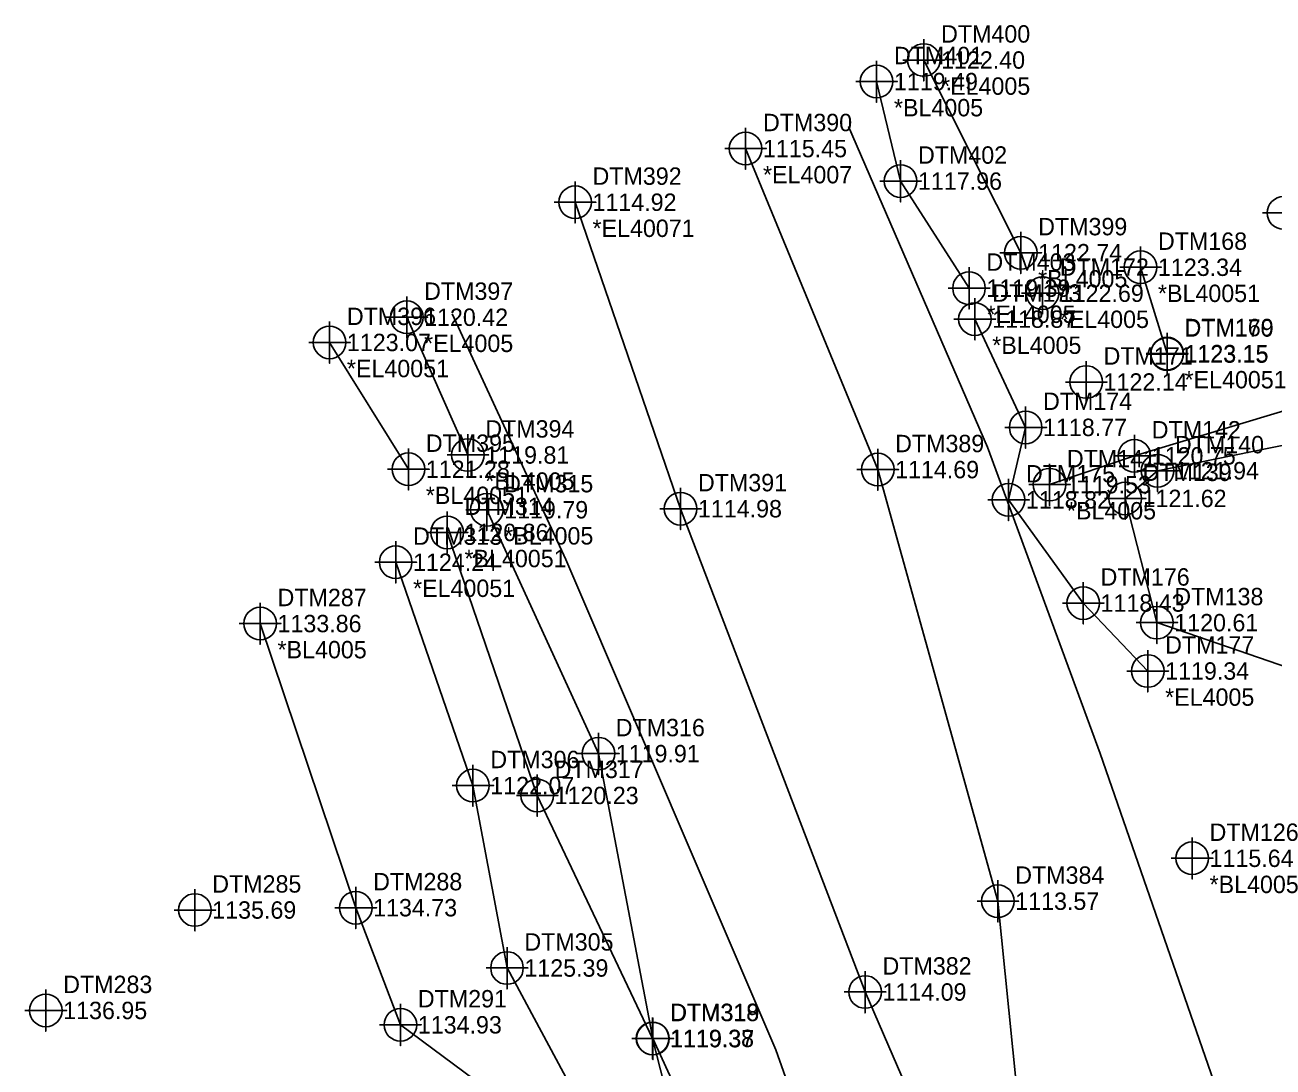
# Model space of a CAD drawing. Extents: x 1286409 to 1286829, y 857931 to 858308.
# Drawn here: x 1286469.6 to 1286649.1, y 858156.8 to 858306.7 of the extents above; entities that cross this region are included whole.
import ezdxf

# ---------------------------------------------------------------- set-up
doc = ezdxf.new("R2010")
doc.units = 0
for name, color, linetype in [('Exist DTM Breakline', 7, 'Continuous'), ('Exist DTM Breakline Cogo Comment', 7, 'Continuous'), ('Exist DTM Breakline Cogo Elevation', 7, 'Continuous'), ('Exist DTM Breakline Cogo Number', 7, 'Continuous'), ('Exist DTM Breakline Cogo Point CELL', 7, 'Continuous'), ('Exist DTM Breakline Underwater', 7, 'Continuous'), ('Exist DTM Breakline Underwater Cogo Comment', 7, 'Continuous'), ('Exist DTM Breakline Underwater Cogo Elevation', 7, 'Continuous'), ('Exist DTM Breakline Underwater Cogo Number', 7, 'Continuous'), ('Exist DTM Breakline Underwater Cogo Point CELL', 7, 'Continuous'), ('Exist DTM Regular Point CELL', 7, 'Continuous'), ('Exist DTM Regular Point Cogo Elevation', 7, 'Continuous'), ('Exist DTM Regular Point Cogo Number', 7, 'Continuous'), ('Exist Hydro Stream or Body of Water', 7, 'Continuous')]:
    doc.layers.add(name, color=color, linetype=linetype)

msp = doc.modelspace()

# ---------------------------------------------------------------- linework, layer by layer
at = {"layer": 'Exist DTM Breakline'}
for p, q in [((1286612.819, 858273.914), (1286598.853, 858301.617)), ((1286630.051, 858271.823), (1286633.873, 858259.409)), ((1286533.288, 858244.832), (1286524.485, 858264.635)), ((1286524.734, 858242.78), (1286513.381, 858261.013))]:
    msp.add_line(p, q, dxfattribs=at)
for points in [[(1286592.072, 858298.515), (1286595.532, 858284.207), (1286605.37, 858268.817)], [(1286606.21, 858264.364), (1286613.519, 858248.803), (1286611.058, 858238.384), (1286621.795, 858223.547), (1286631.083, 858213.773)], [(1286616.952, 858240.566), (1286629.155, 858244.707), (1286658.287, 858253.478), (1286686.461, 858252.975), (1286698.943, 858257.032), (1286730.846, 858256.269)], [(1286655.768, 858212.7), (1286632.397, 858220.726), (1286627.838, 858238.589), (1286632.493, 858242.571), (1286660.074, 858248.148)], [(1286536.003, 858236.961), (1286552.055, 858201.893), (1286559.903, 858160.92), (1286565.827, 858147.987), (1286576.897, 858124.766), (1286579.562, 858099.067), (1286584.222, 858081.673), (1286607.668, 858049.163), (1286601.672, 858086.174)], [(1286530.298, 858233.7), (1286543.261, 858195.881), (1286559.854, 858160.955), (1286563.292, 858147.427), (1286569.804, 858128.536), (1286569.528, 858112.107), (1286564.126, 858113.252), (1286558.412, 858113.755), (1286552.418, 858104.363), (1286554.757, 858095.462), (1286567.776, 858091.209), (1286569.105, 858068.653), (1286573.239, 858056.109), (1286586.738, 858049.307), (1286601.784, 858041.235), (1286607.702, 858042.424), (1286614.823, 858014.95)], [(1286549.858, 858150.722), (1286538.911, 858171.077), (1286534.01, 858197.304), (1286522.897, 858229.418)], [(1286503.403, 858220.596), (1286517.153, 858179.744), (1286523.583, 858162.909), (1286544.969, 858147.024), (1286522.671, 858133.149)]]:
    msp.add_lwpolyline(points, dxfattribs=at)
at = {"layer": 'Exist DTM Breakline Cogo Point CELL'}
for points in [[(1286598.853, 858304.617), (1286598.853, 858298.617), (1286598.853, 858301.617), (1286601.853, 858301.617), (1286595.853, 858301.617)], [(1286592.072, 858301.515), (1286592.072, 858295.515), (1286592.072, 858298.515), (1286595.072, 858298.515), (1286589.072, 858298.515)], [(1286595.532, 858287.207), (1286595.532, 858281.207), (1286595.532, 858284.207), (1286598.532, 858284.207), (1286592.532, 858284.207)], [(1286650.61, 858282.628), (1286650.61, 858276.628), (1286650.61, 858279.628), (1286653.61, 858279.628), (1286647.61, 858279.628)], [(1286612.819, 858276.914), (1286612.819, 858270.914), (1286612.819, 858273.914), (1286615.819, 858273.914), (1286609.819, 858273.914)], [(1286630.051, 858274.823), (1286630.051, 858268.823), (1286630.051, 858271.823), (1286633.051, 858271.823), (1286627.051, 858271.823)], [(1286605.37, 858271.817), (1286605.37, 858265.817), (1286605.37, 858268.817), (1286608.37, 858268.817), (1286602.37, 858268.817)], [(1286615.929, 858271.092), (1286615.929, 858265.092), (1286615.929, 858268.092), (1286618.929, 858268.092), (1286612.929, 858268.092)], [(1286524.485, 858267.635), (1286524.485, 858261.635), (1286524.485, 858264.635), (1286527.485, 858264.635), (1286521.485, 858264.635)], [(1286606.21, 858267.364), (1286606.21, 858261.364), (1286606.21, 858264.364), (1286609.21, 858264.364), (1286603.21, 858264.364)], [(1286513.381, 858264.013), (1286513.381, 858258.013), (1286513.381, 858261.013), (1286516.381, 858261.013), (1286510.381, 858261.013)], [(1286633.852, 858262.336), (1286633.852, 858256.336), (1286633.852, 858259.336), (1286636.852, 858259.336), (1286630.852, 858259.336)], [(1286633.873, 858262.409), (1286633.873, 858256.409), (1286633.873, 858259.409), (1286636.873, 858259.409), (1286630.873, 858259.409)], [(1286622.228, 858258.324), (1286622.228, 858252.324), (1286622.228, 858255.324), (1286625.228, 858255.324), (1286619.228, 858255.324)], [(1286613.519, 858251.803), (1286613.519, 858245.803), (1286613.519, 858248.803), (1286616.519, 858248.803), (1286610.519, 858248.803)], [(1286533.288, 858247.832), (1286533.288, 858241.832), (1286533.288, 858244.832), (1286536.288, 858244.832), (1286530.288, 858244.832)], [(1286629.155, 858247.707), (1286629.155, 858241.707), (1286629.155, 858244.707), (1286632.155, 858244.707), (1286626.155, 858244.707)], [(1286524.734, 858245.78), (1286524.734, 858239.78), (1286524.734, 858242.78), (1286527.734, 858242.78), (1286521.734, 858242.78)], [(1286632.493, 858245.571), (1286632.493, 858239.571), (1286632.493, 858242.571), (1286635.493, 858242.571), (1286629.493, 858242.571)], [(1286616.952, 858243.566), (1286616.952, 858237.566), (1286616.952, 858240.566), (1286619.952, 858240.566), (1286613.952, 858240.566)], [(1286611.058, 858241.384), (1286611.058, 858235.384), (1286611.058, 858238.384), (1286614.058, 858238.384), (1286608.058, 858238.384)], [(1286627.838, 858241.589), (1286627.838, 858235.589), (1286627.838, 858238.589), (1286630.838, 858238.589), (1286624.838, 858238.589)], [(1286536.003, 858239.961), (1286536.003, 858233.961), (1286536.003, 858236.961), (1286539.003, 858236.961), (1286533.003, 858236.961)], [(1286530.298, 858236.7), (1286530.298, 858230.7), (1286530.298, 858233.7), (1286533.298, 858233.7), (1286527.298, 858233.7)], [(1286522.897, 858232.418), (1286522.897, 858226.418), (1286522.897, 858229.418), (1286525.897, 858229.418), (1286519.897, 858229.418)], [(1286621.795, 858226.547), (1286621.795, 858220.547), (1286621.795, 858223.547), (1286624.795, 858223.547), (1286618.795, 858223.547)], [(1286503.403, 858223.596), (1286503.403, 858217.596), (1286503.403, 858220.596), (1286506.403, 858220.596), (1286500.403, 858220.596)], [(1286632.397, 858223.726), (1286632.397, 858217.726), (1286632.397, 858220.726), (1286635.397, 858220.726), (1286629.397, 858220.726)], [(1286631.083, 858216.773), (1286631.083, 858210.773), (1286631.083, 858213.773), (1286634.083, 858213.773), (1286628.083, 858213.773)], [(1286552.055, 858204.893), (1286552.055, 858198.893), (1286552.055, 858201.893), (1286555.055, 858201.893), (1286549.055, 858201.893)], [(1286534.01, 858200.304), (1286534.01, 858194.304), (1286534.01, 858197.304), (1286537.01, 858197.304), (1286531.01, 858197.304)], [(1286543.261, 858198.881), (1286543.261, 858192.881), (1286543.261, 858195.881), (1286546.261, 858195.881), (1286540.261, 858195.881)], [(1286637.473, 858189.849), (1286637.473, 858183.849), (1286637.473, 858186.849), (1286640.473, 858186.849), (1286634.473, 858186.849)], [(1286517.153, 858182.744), (1286517.153, 858176.744), (1286517.153, 858179.744), (1286520.153, 858179.744), (1286514.153, 858179.744)], [(1286538.911, 858174.077), (1286538.911, 858168.077), (1286538.911, 858171.077), (1286541.911, 858171.077), (1286535.911, 858171.077)], [(1286523.583, 858165.909), (1286523.583, 858159.909), (1286523.583, 858162.909), (1286526.583, 858162.909), (1286520.583, 858162.909)], [(1286559.854, 858163.955), (1286559.854, 858157.955), (1286559.854, 858160.955), (1286562.854, 858160.955), (1286556.854, 858160.955)], [(1286559.903, 858163.92), (1286559.903, 858157.92), (1286559.903, 858160.92), (1286562.903, 858160.92), (1286556.903, 858160.92)]]:
    msp.add_lwpolyline(points, dxfattribs=at)
for centre in [(1286598.853, 858301.617), (1286592.072, 858298.515), (1286595.532, 858284.207), (1286650.61, 858279.628), (1286612.819, 858273.914), (1286630.051, 858271.823), (1286605.37, 858268.817), (1286615.929, 858268.092), (1286524.485, 858264.635), (1286606.21, 858264.364), (1286513.381, 858261.013), (1286633.852, 858259.336), (1286633.873, 858259.409), (1286622.228, 858255.324), (1286613.519, 858248.803), (1286533.288, 858244.832), (1286629.155, 858244.707), (1286524.734, 858242.78), (1286632.493, 858242.571), (1286616.952, 858240.566), (1286611.058, 858238.384), (1286627.838, 858238.589), (1286536.003, 858236.961), (1286530.298, 858233.7), (1286522.897, 858229.418), (1286621.795, 858223.547), (1286503.403, 858220.596), (1286632.397, 858220.726), (1286631.083, 858213.773), (1286552.055, 858201.893), (1286534.01, 858197.304), (1286543.261, 858195.881), (1286637.473, 858186.849), (1286517.153, 858179.744), (1286538.911, 858171.077), (1286523.583, 858162.909), (1286559.854, 858160.955), (1286559.903, 858160.92)]:
    msp.add_circle(centre, 2.344, dxfattribs=at)
at = {"layer": 'Exist DTM Breakline Underwater'}
for points in [[(1286669.815, 858058.251), (1286654.631, 858100.703), (1286613.243, 858143.649), (1286609.52, 858180.682), (1286592.241, 858242.731), (1286573.236, 858288.883)], [(1286646.614, 858037.087), (1286629.153, 858089.196), (1286603.619, 858137.215), (1286590.426, 858167.626), (1286563.88, 858237.106), (1286548.712, 858281.174)]]:
    msp.add_lwpolyline(points, dxfattribs=at)
at = {"layer": 'Exist DTM Breakline Underwater Cogo Point CELL'}
for points in [[(1286573.236, 858291.883), (1286573.236, 858285.883), (1286573.236, 858288.883), (1286576.236, 858288.883), (1286570.236, 858288.883)], [(1286548.712, 858284.174), (1286548.712, 858278.174), (1286548.712, 858281.174), (1286551.712, 858281.174), (1286545.712, 858281.174)], [(1286592.241, 858245.731), (1286592.241, 858239.731), (1286592.241, 858242.731), (1286595.241, 858242.731), (1286589.241, 858242.731)], [(1286563.88, 858240.106), (1286563.88, 858234.106), (1286563.88, 858237.106), (1286566.88, 858237.106), (1286560.88, 858237.106)], [(1286609.52, 858183.682), (1286609.52, 858177.682), (1286609.52, 858180.682), (1286612.52, 858180.682), (1286606.52, 858180.682)], [(1286590.426, 858170.626), (1286590.426, 858164.626), (1286590.426, 858167.626), (1286593.426, 858167.626), (1286587.426, 858167.626)]]:
    msp.add_lwpolyline(points, dxfattribs=at)
for centre in [(1286573.236, 858288.883), (1286548.712, 858281.174), (1286592.241, 858242.731), (1286563.88, 858237.106), (1286609.52, 858180.682), (1286590.426, 858167.626)]:
    msp.add_circle(centre, 2.344, dxfattribs=at)
at = {"layer": 'Exist DTM Regular Point CELL'}
for points in [[(1286494.01, 858182.414), (1286494.01, 858176.414), (1286494.01, 858179.414), (1286497.01, 858179.414), (1286491.01, 858179.414)], [(1286472.57, 858167.972), (1286472.57, 858161.972), (1286472.57, 858164.972), (1286475.57, 858164.972), (1286469.57, 858164.972)]]:
    msp.add_lwpolyline(points, dxfattribs=at)
for centre in [(1286494.01, 858179.414), (1286472.57, 858164.972)]:
    msp.add_circle(centre, 2.344, dxfattribs=at)
at = {"layer": 'Exist Hydro Stream or Body of Water'}
for points in [[(1286685.865, 858065.012), (1286665.776, 858106.892), (1286641.007, 858153.512), (1286624.223, 858201.931), (1286608.049, 858245.959), (1286588.044, 858292.077)], [(1286633.369, 858010.272), (1286619.226, 858059.374), (1286604.574, 858088.843), (1286588.568, 858128.319), (1286577.591, 858159.308), (1286547.36, 858229.805), (1286531.042, 858265.146)]]:
    msp.add_lwpolyline(points, dxfattribs=at)

# ---------------------------------------------------------------- texts
at = {"layer": 'Exist DTM Breakline Cogo Comment'}
for s, p in [('*EL4005', (1286601.353, 858296.617)), ('*BL4005', (1286594.572, 858293.515)), ('*BL4005', (1286615.319, 858268.914)), ('*BL40051', (1286632.551, 858266.823)), ('*EL4005', (1286607.87, 858263.817)), ('*EL4005', (1286618.429, 858263.092)), ('*EL4005', (1286526.985, 858259.635)), ('*BL4005', (1286608.71, 858259.364)), ('*EL40051', (1286515.881, 858256.013)), ('*EL40051', (1286636.373, 858254.409)), ('*BL4005', (1286535.788, 858239.832)), ('*BL40051', (1286527.234, 858237.78)), ('*BL4005', (1286619.452, 858235.566)), ('*BL4005', (1286538.503, 858231.961)), ('*BL40051', (1286532.798, 858228.7)), ('*EL40051', (1286525.397, 858224.418)), ('*BL4005', (1286505.903, 858215.596)), ('*EL4005', (1286633.583, 858208.773)), ('*BL4005', (1286639.973, 858181.849))]:
    msp.add_text(s, height=2.5, dxfattribs=at).set_placement(p)
at = {"layer": 'Exist DTM Breakline Cogo Elevation'}
for s, p in [('1122.40', (1286601.353, 858300.367)), ('1119.49', (1286594.572, 858297.265)), ('1117.96', (1286598.032, 858282.957)), ('1122.74', (1286615.319, 858272.664)), ('1123.34', (1286632.551, 858270.573)), ('1119.39', (1286607.87, 858267.567)), ('1122.69', (1286618.429, 858266.842)), ('1120.42', (1286526.985, 858263.385)), ('1118.87', (1286608.71, 858263.114)), ('1123.07', (1286515.881, 858259.763)), ('1123.15', (1286636.352, 858258.086)), ('1123.15', (1286636.373, 858258.159)), ('1122.14', (1286624.728, 858254.074)), ('1118.77', (1286616.019, 858247.553)), ('1119.81', (1286535.788, 858243.582)), ('1120.75', (1286631.655, 858243.457)), ('1121.28', (1286527.234, 858241.53)), ('1121.94', (1286634.993, 858241.321)), ('1119.53', (1286619.452, 858239.316)), ('1118.82', (1286613.558, 858237.134)), ('1121.62', (1286630.338, 858237.339)), ('1119.79', (1286538.503, 858235.711)), ('1120.86', (1286532.798, 858232.45)), ('1124.24', (1286525.397, 858228.168)), ('1118.43', (1286624.295, 858222.297)), ('1133.86', (1286505.903, 858219.346)), ('1120.61', (1286634.897, 858219.476)), ('1119.34', (1286633.583, 858212.523)), ('1119.91', (1286554.555, 858200.643)), ('1122.07', (1286536.51, 858196.054)), ('1120.23', (1286545.761, 858194.631)), ('1115.64', (1286639.973, 858185.599)), ('1134.73', (1286519.653, 858178.494)), ('1125.39', (1286541.411, 858169.827)), ('1134.93', (1286526.083, 858161.659)), ('1119.38', (1286562.354, 858159.705)), ('1119.37', (1286562.403, 858159.67))]:
    msp.add_text(s, height=2.5, dxfattribs=at).set_placement(p)
at = {"layer": 'Exist DTM Breakline Cogo Number'}
for s, p in [('DTM400', (1286601.353, 858304.117)), ('DTM401', (1286594.572, 858301.015)), ('DTM402', (1286598.032, 858286.707)), ('DTM399', (1286615.319, 858276.414)), ('DTM168', (1286632.551, 858274.323)), ('DTM403', (1286607.87, 858271.317)), ('DTM172', (1286618.429, 858270.592)), ('DTM397', (1286526.985, 858267.135)), ('DTM173', (1286608.71, 858266.864)), ('DTM396', (1286515.881, 858263.513)), ('DTM170', (1286636.352, 858261.836)), ('DTM169', (1286636.373, 858261.909)), ('DTM171', (1286624.728, 858257.824)), ('DTM174', (1286616.019, 858251.303)), ('DTM394', (1286535.788, 858247.332)), ('DTM142', (1286631.655, 858247.207)), ('DTM395', (1286527.234, 858245.28)), ('DTM140', (1286634.993, 858245.071)), ('DTM141', (1286619.452, 858243.066)), ('DTM175', (1286613.558, 858240.884)), ('DTM139', (1286630.338, 858241.089)), ('DTM315', (1286538.503, 858239.461)), ('DTM314', (1286532.798, 858236.2)), ('DTM313', (1286525.397, 858231.918)), ('DTM176', (1286624.295, 858226.047)), ('DTM287', (1286505.903, 858223.096)), ('DTM138', (1286634.897, 858223.226)), ('DTM177', (1286633.583, 858216.273)), ('DTM316', (1286554.555, 858204.393)), ('DTM306', (1286536.51, 858199.804)), ('DTM317', (1286545.761, 858198.381)), ('DTM126', (1286639.973, 858189.349)), ('DTM288', (1286519.653, 858182.244)), ('DTM305', (1286541.411, 858173.577)), ('DTM291', (1286526.083, 858165.409)), ('DTM318', (1286562.354, 858163.455)), ('DTM319', (1286562.403, 858163.42))]:
    msp.add_text(s, height=2.5, dxfattribs=at).set_placement(p)
at = {"layer": 'Exist DTM Breakline Underwater Cogo Comment'}
for s, p in [('*EL4007', (1286575.736, 858283.883)), ('*EL40071', (1286551.212, 858276.174))]:
    msp.add_text(s, height=2.5, dxfattribs=at).set_placement(p)
at = {"layer": 'Exist DTM Breakline Underwater Cogo Elevation'}
for s, p in [('1115.45', (1286575.736, 858287.633)), ('1114.92', (1286551.212, 858279.924)), ('1114.69', (1286594.741, 858241.481)), ('1114.98', (1286566.38, 858235.856)), ('1113.57', (1286612.02, 858179.432)), ('1114.09', (1286592.926, 858166.376))]:
    msp.add_text(s, height=2.5, dxfattribs=at).set_placement(p)
at = {"layer": 'Exist DTM Breakline Underwater Cogo Number'}
for s, p in [('DTM390', (1286575.736, 858291.383)), ('DTM392', (1286551.212, 858283.674)), ('DTM389', (1286594.741, 858245.231)), ('DTM391', (1286566.38, 858239.606)), ('DTM384', (1286612.02, 858183.182)), ('DTM382', (1286592.926, 858170.126))]:
    msp.add_text(s, height=2.5, dxfattribs=at).set_placement(p)
at = {"layer": 'Exist DTM Regular Point Cogo Elevation'}
for s, p in [('1135.69', (1286496.51, 858178.164)), ('1136.95', (1286475.07, 858163.722))]:
    msp.add_text(s, height=2.5, dxfattribs=at).set_placement(p)
at = {"layer": 'Exist DTM Regular Point Cogo Number'}
for s, p in [('DTM285', (1286496.51, 858181.914)), ('DTM283', (1286475.07, 858167.472))]:
    msp.add_text(s, height=2.5, dxfattribs=at).set_placement(p)

doc.saveas('drawing.dxf')
